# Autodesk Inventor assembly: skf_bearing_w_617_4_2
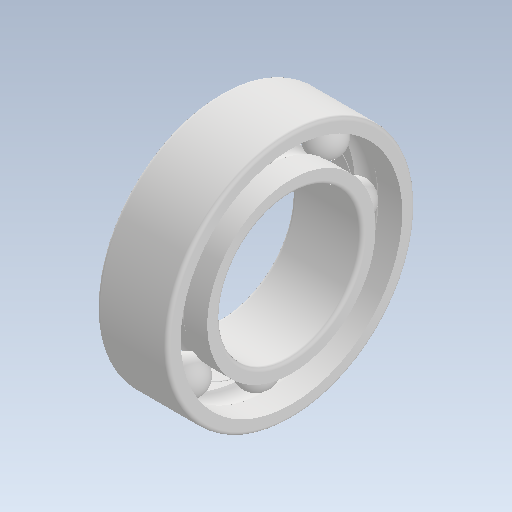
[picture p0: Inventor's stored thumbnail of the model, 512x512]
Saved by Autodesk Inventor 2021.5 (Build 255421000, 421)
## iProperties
Company: TraceParts S.A.
Created: 2023-11
Part Number: skf_bearing_w_617_4_2
Checked By: TraceParts S.A.
Catalog Web Link: www.traceparts.com
Document SubType Name: Assembly
Designer: TraceParts
Author: TraceParts
Sending System: TraceParts v2
Major Version: 6.0
Minor Version: 0.0
Format Version: 0.0
Product Id: TraceParts v2
REFERENCE: W 617/4
SUPPLIER: SKF
DESIGN: Stainless steel single row deep groove ball bearing, Bore Ø 4 mm, Outside Ø 7 mm
MASS: 0.0002
TraceParts.PartNumber: 10-27092016-074236
TraceParts.PartVersion: 1.3.1
TraceParts.InstanceId: 10-27092016-0742369K9II9L2W0YD7GYJ7HMTTV4CI
TraceParts.PartTitle: Deep groove ball bearings, single row, stainless steel
TRACEPARTS: TRACEPARTS
TraceParts.PartLanguage: en
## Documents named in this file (4)
- C:\TPO v2\SharedFS\Outgoing\skf_bearing_w_617_4_2.iam
- C:\TPO v2\SharedFS\Outgoing\skf_bearing_w_617_4_2_01.ipt
- C:\TPO v2\SharedFS\Outgoing\skf_bearing_w_617_4_2_02.ipt
- C:\TPO v2\SharedFS\Outgoing\skf_bearing_w_617_4_2_03.ipt
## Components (3 placed, 3 different names)
1. skf_bearing_w_617_4_2_Temp_1:1
2. skf_bearing_w_617_4_2_Temp_2:1
3. skf_bearing_w_617_4_2_Temp_3:1
